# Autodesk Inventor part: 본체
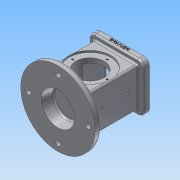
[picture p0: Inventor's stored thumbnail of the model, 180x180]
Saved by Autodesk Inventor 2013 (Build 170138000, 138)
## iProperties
Created: 2018-10
Part Number: 본체
Material: 알루미늄 6061
Document SubType Name: Modeling
Designer: Administrator
Density: 2.71 g/cm^3
Mass: 988.222 g
Surface Area: 743.905 cm^2
Volume: 364.657 cm^3
Author: Administrator
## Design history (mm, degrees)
sketch "스케치1"
  geometry: L1 (-37, 33)-(37, 33); L2 (37, 33)-(37, -33); L3 (37, -33)-(-37, -33); L4 (-37, -33)-(-37, 33); L5 (-37, 33)-(37, -33); L6 (37, 33)-(-37, -33); 1 further point
  constraints: 12 end point, 2 midpoint, 2 parallel, 1 horizontal, 1 perpendicular
  dimensions: "d0" = 74 distance of L2.end L3.end; "d1" = 66 distance of L1.end L2.end
extrude "돌출1" new body sketch "스케치1" stored distance "d2" = 108; taper "d3" = 0 deg
sketch "스케치2"
  geometry: L1 (37, 33)-(-37, 33) reference; L2 (-37, 33)-(-37, -33) reference; L3 (-37, -33)-(37, -33) reference; L4 (37, -33)-(37, 33) reference; C1 r 62.5 at (0, 0); 1 further point
  constraints: 1 centre point, 1 coincident
  dimensions: "d4" = 125 diameter of C1
extrude "돌출2" join sketch "스케치2" distance "d5" = 10; taper "d6" = 0 deg
sketch "스케치3"
  geometry: L1 (37, -33)-(37, 33) reference; L2 (37, 33)-(-37, 33) reference; L3 (-37, 33)-(-37, -33) reference; L4 (-37, -33)-(37, -33) reference; L5 (-46, -41)-(46, -41); L6 (46, -41)-(46, 41); L7 (46, 41)-(-46, 41); L8 (-46, 41)-(-46, -41); L9 (-46, -41)-(46, 41); L10 (46, -41)-(-46, 41); A1 r 10 centre (27, -23) between (27, -33) and (37, -23) reference; A2 r 10 centre (27, 23) between (37, 23) and (27, 33) reference; A3 r 10 centre (-27, 23) between (-27, 33) and (-37, 23) reference; A4 r 10 centre (-27, -23) between (-37, -23) and (-27, -33) reference; 1 further point
  constraints: 12 end point, 2 midpoint, 2 parallel, 1 horizontal, 1 perpendicular
  dimensions: "d8" = 92 distance of L7.end L6.end; "d9" = 82 distance of L6.end L5.end
extrude "돌출3" join sketch "스케치3" distance "d10" = 10; taper "d11" = 0 deg
fillet "모깎기2" dims "d12" = 10
fillet "모깎기3" dims "d13" = 3
fillet "모깎기4" dims "d14" = 3
sketch "스케치4"
  geometry: A1 r 10 centre (-36, 31) between (-36, 41) and (-46, 31) reference; 2 further points
  constraints: 1 coincident
hole "구멍1" sketch "스케치4" at (-36, 31) diameter "d15" = 3.242; stored, may be unused: countersink angle "d19" = 90 deg, drill point angle "d21" = 118 deg; dims "d16" = 4, "d17" = 4, "d18" = 2, "d20" = 6
sketch "스케치6"
  geometry: L1 (96.5, -13)-(-28.5, -13) reference; C1 r 35 at (34, 41); 1 further point
  constraints: 1 centre point, 1 coincident
  dimensions: "d24" = 70 diameter of C1; "d25" = 54 distance from line of L1 C1.centre
extrude "돌출4" cut sketch "스케치6" distance "d26" = 3; taper "d27" = 0 deg
sketch "스케치7"
  geometry: C1 r 35 at (0, 0) reference; 1 further point
  constraints: 1 vertical alignment
  dimensions: "d28" = 29 distance of C1.centre point (0, 29)
hole "구멍2" sketch "스케치7" at (0, 29) diameter "d29" = 3.242; stored, may be unused: countersink angle "d33" = 90 deg, drill point angle "d35" = 118 deg; dims "d30" = 4, "d31" = 4, "d32" = 2, "d34" = 6
fillet "모깎기5" dims "d39" = 3
sketch "스케치8"
  geometry: C1 r 59.5 at (0, 0) reference; 1 further point
  constraints: 1 vertical alignment
  dimensions: "d40" = 50 distance of C1.centre point (0, 50)
hole "구멍3" sketch "스케치8" at (0, 50) diameter "d41" = 9; stored, may be unused: countersink angle "d45" = 90 deg, drill point angle "d47" = 118 deg; dims "d42" = 4, "d43" = 4, "d44" = 2, "d46" = 6
sketch "스케치9"
  geometry: C1 r 62.5 at (0, 0) reference; C2 r 28 at (0, 0)
  constraints: 1 centre point, 1 coincident
  dimensions: "d51" = 56 diameter of C2
extrude "돌출5" cut sketch "스케치9" distance "d52" = 18; taper "d53" = -10 deg
fillet "모깎기6" dims "d54" = 3
sketch "스케치11"
  geometry: L1 (26, -26)-(-26, -26); L2 (-26, -26)-(-26, 26); L3 (-26, 26)-(26, 26); L4 (26, 26)-(26, -26); L5 (26, -26)-(-26, 26); L6 (-26, -26)-(26, 26); 1 further point
  constraints: 12 end point, 2 midpoint, 2 parallel, 1 horizontal, 1 perpendicular
  dimensions: "d58" = 52 distance of L2.end L3.end; "d59" = 52 distance of L1.end L2.end
extrude "돌출7" cut sketch "스케치11" distance "d60" = 8; taper "d61" = 0 deg
sketch "스케치12"
  geometry: L1 (-22, -22)-(22, -22); L2 (22, -22)-(22, 22); L3 (22, 22)-(-22, 22); L4 (-22, 22)-(-22, -22); L5 (-22, -22)-(22, 22); L6 (22, -22)-(-22, 22); 1 further point
  constraints: 12 end point, 2 midpoint, 2 parallel, 1 horizontal, 1 perpendicular
  dimensions: "d62" = 44 distance of L3.end L2.end; "d63" = 44 distance of L2.end L1.end
extrude "돌출8" cut sketch "스케치12" distance "d64" = 74; taper "d65" = 0 deg
fillet "모깎기7" dims "d66" = 3
fillet "모깎기8" dims "d67" = 3
chamfer "모따기1" distance "d68" = 1; stored, may be unused: second distance "d69" = 2, angle "d70" = 45 deg
sketch "스케치13"
  geometry: C1 r 35 at (0, 0) reference; C2 r 24 at (0, 0)
  constraints: 1 centre point, 1 coincident
  dimensions: "d71" = 48 diameter of C2
extrude "돌출9" cut sketch "스케치13" stored distance "d72" = 74; taper "d73" = 0 deg
sketch "스케치14"
  geometry: L1 (32.5, -13)-(-92.5, -13) reference; 3 further points
  constraints: 1 midpoint, 1 vertical alignment
  dimensions: "d74" = 37 distance from line of L1 point (-30, 24)
hole "구멍4" sketch "스케치14" at (-30, 24) diameter "d75" = 4.134; stored, may be unused: countersink angle "d79" = 90 deg, drill point angle "d81" = 0 deg; dims "d76" = 4, "d77" = 4, "d78" = 2, "d80" = 6
fillet "모깎기9" dims "d85" = 3
sketch "스케치15"
  geometry: L1 (0, 0)-(72, 0) reference; L2 (-10, 0)-(-10, -7) reference; 2 further points
  constraints: 1 other
  dimensions: "d86" = 46 distance from line of point (36, -4) L2; "d87" = 4 distance from line of L1 point (36, -4)
feature "엠보싱1" sketch "스케치15" dims "d0" = 74, "d1" = 66, "d88" = 0.5, "d89" = 0
node "솔리드1"
mirror "대칭1"
mirror "대칭2"
mirror "대칭3"
pattern_circular "원형 패턴1" dims angle "d37" = 360 deg
mirror "대칭4"
pattern_circular "원형 패턴2" dims angle "d49" = 360 deg
pattern_linear "직사각형 패턴1" dims "d84" = 43
